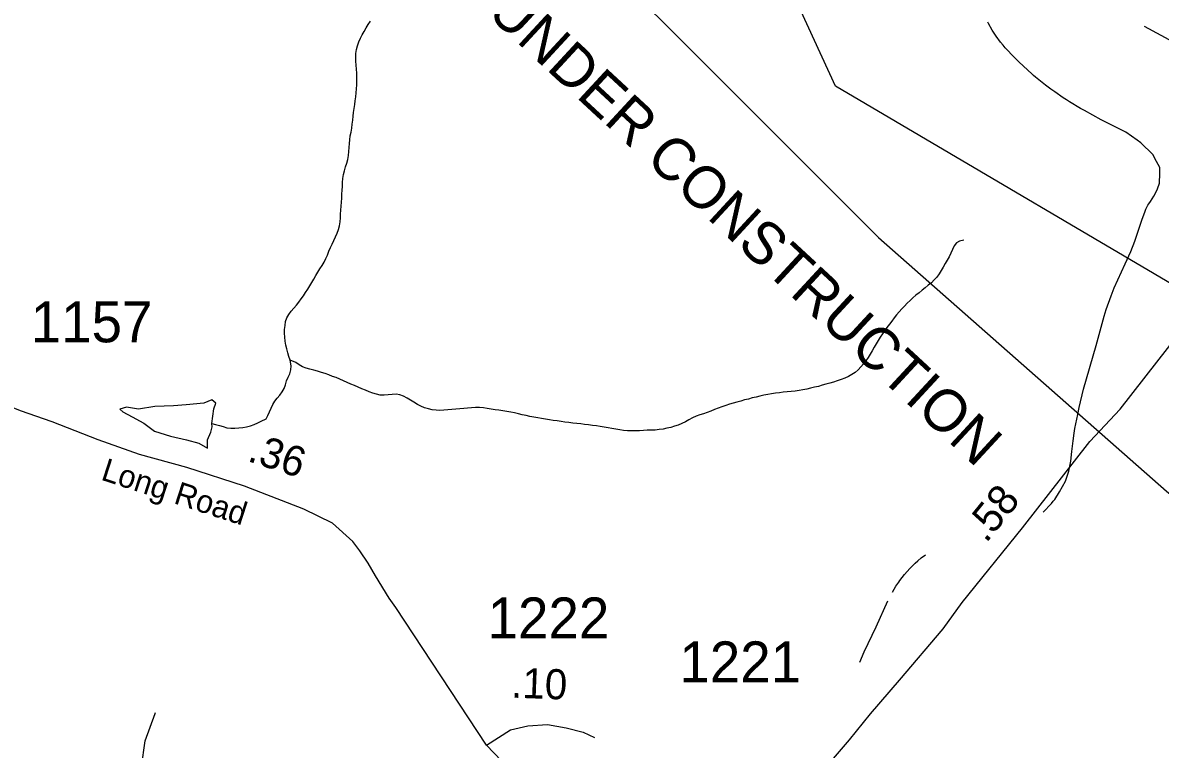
# Model space of a CAD drawing. Extents: x 1950930 to 2061844, y 904556 to 1017002.
# Drawn here: x 1991711 to 1996439, y 955325 to 958343 of the extents above; entities that cross this region are included whole.
import ezdxf

# ---------------------------------------------------------------- set-up
doc = ezdxf.new("R2010")
doc.units = 0
for name, color, linetype in [('Exist Hydrographic Creek Single Shore', 7, 'Continuous'), ('Exist Hydrographic Misc Water Feature', 7, 'Continuous'), ('Exist Road Primary Interstate Shield CELL', 7, 'Continuous'), ('Exist Road Primary NC Attributed', 7, 'Continuous'), ('Exist Road Primary NC Service Mileage Hundredths English Label', 7, 'Continuous'), ('Exist Road Primary US Structure Standard Bridge CELL', 7, 'Continuous'), ('Exist Road Secondary Structure Standard Bridge Number Label', 7, 'Continuous'), ('Exist Road Secondary Type 51 Attributed', 7, 'Continuous'), ('Exist Road Secondary Type 51 Label', 7, 'Continuous'), ('Exist Road Secondary Type 51 Number Label', 7, 'Continuous'), ('Prop Road Primary NC Projected', 7, 'Continuous')]:
    doc.layers.add(name, color=color, linetype=linetype)

msp = doc.modelspace()

# ---------------------------------------------------------------- linework, layer by layer
at = {"layer": 'Exist Hydrographic Creek Single Shore'}
for points in [[(1992823.3, 956941), (1992817.9, 956956.6), (1992812.8, 956972.3), (1992808.9, 956988), (1992805.4, 957003.7), (1992802.6, 957020.2), (1992800.5, 957036.6), (1992799.7, 957053), (1992799.9, 957069.5), (1992801.5, 957085.9), (1992803.6, 957102.2), (1992808.5, 957117.7), (1992816.7, 957131.6), (1992827, 957144.4), (1992838, 957157.3), (1992849.1, 957169.4), (1992859, 957182.3), (1992868.6, 957196), (1992877.8, 957209), (1992887, 957222.8), (1992895.9, 957236.5), (1992904.7, 957250.3), (1992913.3, 957264.8), (1992921.7, 957278.7), (1992929.7, 957293.2), (1992938.1, 957307), (1992946.5, 957320.8), (1992955.3, 957335.4), (1992963.7, 957349.1), (1992971.1, 957363.8), (1992977.7, 957378.4), (1992984, 957393.9), (1992990.4, 957409.3), (1992997, 957424), (1993003.9, 957438.6), (1993010.7, 957454), (1993017.5, 957468.7), (1993024.2, 957484), (1993028.3, 957499.6), (1993030.2, 957515.9), (1993031.4, 957532.4), (1993032.6, 957548.7), (1993033.7, 957565.1), (1993034.7, 957581.5), (1993035.7, 957597.9), (1993036.9, 957614.2), (1993038, 957630.8), (1993038.8, 957647.1), (1993039.6, 957663.5), (1993040.6, 957679.9), (1993042.3, 957696.2), (1993044.3, 957712.6), (1993048.2, 957728.1), (1993052.9, 957744.4), (1993057.9, 957759.9), (1993062, 957775.4), (1993064.8, 957791.8), (1993066.5, 957808.1), (1993067.7, 957824.5), (1993068.7, 957840.9), (1993070.4, 957857.2), (1993072.8, 957873.6), (1993075.7, 957889.1), (1993078.8, 957905.5), (1993081, 957921.9), (1993082.9, 957938.2), (1993084.5, 957954.6), (1993086.4, 957971), (1993088.2, 957987.3), (1993090.9, 958003.7), (1993093.3, 958019.3), (1993095.2, 958035.6), (1993097, 958052), (1993098, 958068.4), (1993099.3, 958084.7), (1993100.1, 958101.1), (1993100.1, 958117.5), (1993099.3, 958134.1), (1993098, 958150.5), (1993096.4, 958166.9), (1993095.4, 958183.3), (1993095.2, 958199.8), (1993095.6, 958216.1), (1993098, 958232.5), (1993102.4, 958248), (1993107.9, 958263.4), (1993114.7, 958278.9), (1993121.8, 958293.6), (1993130, 958307.3), (1993138.9, 958321.9), (1993147.5, 958335.6), (1993156.1, 958349.5)], [(1992722.8, 956697.8), (1992730.6, 956712.3), (1992737.4, 956727), (1992744.1, 956741.6), (1992751.3, 956757), (1992759.3, 956770.9), (1992769.1, 956783.8), (1992779.8, 956796.7), (1992789.2, 956809.6), (1992797.4, 956824.3), (1992803, 956839.7), (1992807.3, 956856), (1992813.8, 956870.6), (1992820.8, 956885.3), (1992824.9, 956901.6), (1992827.2, 956917.9), (1992823.3, 956941)], [(1994307, 956650.2), (1994290.6, 956649.8), (1994274.2, 956648.5), (1994257.8, 956647.9), (1994241.4, 956647.4), (1994224.8, 956647.8), (1994208.6, 956649.8), (1994192.4, 956651.7), (1994176.2, 956654.6), (1994160.2, 956657.4), (1994144, 956661), (1994127.8, 956663.7), (1994111.8, 956666.6), (1994095.4, 956668.5), (1994079.2, 956670.5), (1994062.8, 956672.5), (1994046.4, 956674.5), (1994030.2, 956676.4), (1994013.8, 956678.5), (1993997.6, 956680.3), (1993981.4, 956682.4), (1993965, 956684.3), (1993948.8, 956687.2), (1993932.6, 956689.2), (1993916.4, 956691.1), (1993900.2, 956694), (1993883.8, 956696.7), (1993867.6, 956698.7), (1993851.6, 956701.5), (1993835.4, 956705.1), (1993819.4, 956707.9), (1993803.4, 956711.5), (1993787.4, 956715.1), (1993771.2, 956718.8), (1993755.2, 956722.4), (1993739.2, 956725.1), (1993722.8, 956727.9), (1993706.6, 956730.8), (1993690.4, 956733.5), (1993674.4, 956735.5), (1993658.3, 956738.4), (1993641.8, 956741.1), (1993625.9, 956743.9), (1993609.4, 956745), (1993593, 956744.5), (1993576.8, 956744.1), (1993560.2, 956742.8), (1993544, 956740.7), (1993527.6, 956739.4), (1993511.2, 956738.1), (1993494.8, 956736.7), (1993478.2, 956735.4), (1993461.8, 956733.3), (1993445.4, 956732.8), (1993429.2, 956733.2), (1993413, 956735.2), (1993397.2, 956738.8), (1993381.4, 956744), (1993366.1, 956751), (1993351.5, 956757.7), (1993336.9, 956766.4), (1993323, 956774.8), (1993308.6, 956784.1), (1993294.3, 956791.8), (1993279.1, 956797), (1993263.7, 956799.8), (1993246.9, 956799.3), (1993230.3, 956797.2), (1993213.5, 956796), (1993197.3, 956796.3), (1993181.7, 956799.9), (1993165.9, 956805.1), (1993150.5, 956810.3), (1993135.4, 956816.4), (1993120.2, 956822.4), (1993104.8, 956829.3), (1993089.6, 956836.3), (1993074.7, 956842.2), (1993059.3, 956848.3), (1993044.5, 956855.1), (1993029.6, 956862), (1993014.4, 956869), (1992999.2, 956874.2), (1992983.8, 956880.3), (1992968.2, 956885.5), (1992952.5, 956890.7), (1992936.9, 956895.2), (1992920.9, 956899.6), (1992905.1, 956904), (1992889.3, 956908.5), (1992873.9, 956913.7), (1992860, 956922.2), (1992846, 956931.5), (1992823.3, 956941)]]:
    msp.add_lwpolyline(points, dxfattribs=at)
at = {"layer": 'Exist Hydrographic Misc Water Feature'}
for p, q in [((1995724.6, 958340.5), (1995721.9, 958345.8)), ((1996206.6, 957933.2), (1996193.5, 957940.3)), ((1996357.6, 957844.4), (1996343.4, 957854.8)), ((1996425.6, 957648.7), (1996427.3, 957653.3)), ((1996375.6, 957560.7), (1996379.3, 957568.3))]:
    msp.add_line(p, q, dxfattribs=at)
for points in [[(1995757.6, 958286.9), (1995740.6, 958312.7), (1995724.6, 958340.5)], [(1995757.6, 958286.9), (1995740.6, 958312.7), (1995724.6, 958340.5)], [(1995786.1, 958249.4), (1995775.6, 958262.6), (1995757.6, 958286.9)], [(1995786.1, 958249.4), (1995775.6, 958262.6), (1995757.6, 958286.9)], [(1995803.9, 958228.7), (1995794.7, 958238.7), (1995786.1, 958249.4)], [(1995803.9, 958228.7), (1995794.7, 958238.7), (1995786.1, 958249.4)], [(1995912.6, 958124), (1995904.6, 958131), (1995852.7, 958179.1), (1995822.8, 958208.7), (1995803.9, 958228.7)], [(1995912.6, 958124), (1995904.6, 958131), (1995852.7, 958179.1), (1995822.8, 958208.7), (1995803.9, 958228.7)], [(1996000.2, 958055.9), (1995984.6, 958066.9), (1995962.6, 958083.7), (1995920.6, 958117.2), (1995912.6, 958124)], [(1996000.2, 958055.9), (1995984.6, 958066.9), (1995962.6, 958083.7), (1995920.6, 958117.2), (1995912.6, 958124)], [(1996049, 958022.4), (1996035.6, 958030.9), (1996000.2, 958055.9)], [(1996049, 958022.4), (1996035.6, 958030.9), (1996000.2, 958055.9)], [(1996107.6, 957987.5), (1996061.7, 958014.3), (1996049, 958022.4)], [(1996107.6, 957987.5), (1996061.7, 958014.3), (1996049, 958022.4)], [(1996193.5, 957940.3), (1996123.6, 957978.2), (1996107.6, 957987.5)], [(1996193.5, 957940.3), (1996123.6, 957978.2), (1996107.6, 957987.5)], [(1996343.4, 957854.8), (1996296.5, 957889.1), (1996206.6, 957933.2)], [(1996343.4, 957854.8), (1996296.5, 957889.1), (1996206.6, 957933.2)], [(1996423.8, 957767.1), (1996407.6, 957796.3), (1996357.6, 957844.4)], [(1996423.8, 957767.1), (1996407.6, 957796.3), (1996357.6, 957844.4)], [(1996436.9, 957716.4), (1996437.7, 957741.9), (1996423.8, 957767.1)], [(1996436.9, 957716.4), (1996437.7, 957741.9), (1996423.8, 957767.1)], [(1996427.3, 957653.3), (1996435.9, 957677.2), (1996436.9, 957716.4)], [(1996427.3, 957653.3), (1996435.9, 957677.2), (1996436.9, 957716.4)], [(1996405.5, 957612.3), (1996411.9, 957622.3), (1996425.6, 957648.7)], [(1996405.5, 957612.3), (1996411.9, 957622.3), (1996425.6, 957648.7)], [(1996379.3, 957568.3), (1996387.7, 957585.4), (1996392, 957591.5)], [(1996379.3, 957568.3), (1996387.7, 957585.4), (1996392, 957591.5)], [(1996392, 957591.5), (1996398.4, 957600.9), (1996405.5, 957612.3)], [(1996392, 957591.5), (1996398.4, 957600.9), (1996405.5, 957612.3)], [(1996293.2, 957342), (1996316.5, 957392.6), (1996333.6, 957435.9), (1996362.7, 957523.5), (1996375.6, 957560.7)], [(1995622.2, 957440.2), (1995605.2, 957436.5), (1995591.5, 957429.4), (1995582.9, 957416.4), (1995575.3, 957401.8), (1995568.3, 957386.3), (1995561.5, 957370.9), (1995553.5, 957356.3), (1995545.5, 957342.5), (1995536.9, 957327.9), (1995528.3, 957314.2), (1995519.7, 957300.3), (1995510.1, 957286.6), (1995499.4, 957274.6), (1995487.7, 957263.3), (1995474.6, 957252.9), (1995461.7, 957242.5), (1995449, 957233), (1995436.3, 957221.7), (1995423.7, 957211.3), (1995411.2, 957200.9), (1995398.9, 957189.7), (1995387, 957178.4), (1995375.6, 957166.3), (1995364.5, 957155.1), (1995353.6, 957142.1), (1995343.2, 957130.1), (1995332.9, 957117.2), (1995322.9, 957104.2), (1995313, 957090.4), (1995303.2, 957077.6), (1995293.7, 957064.7), (1995284.3, 957050.9), (1995275.1, 957037.1), (1995266.1, 957023.4), (1995257.9, 957009.5), (1995249.7, 956995), (1995241.9, 956980.4), (1995233.9, 956966.6), (1995224.8, 956952.9), (1995215.2, 956939.1), (1995205, 956926.2), (1995194.3, 956913.3), (1995182.8, 956902), (1995170.7, 956890.8), (1995157.2, 956882), (1995142.6, 956874.1), (1995127.4, 956867.1), (1995112.1, 956861.6), (1995096.5, 956856.2), (1995081.1, 956850.7), (1995065.3, 956846.2), (1995049.3, 956841.6), (1995033.7, 956837), (1995018, 956832.4), (1995001.8, 956828.7), (1994986, 956824.9), (1994969.8, 956821.1), (1994953.8, 956818.1), (1994937.8, 956816), (1994921.4, 956813.1), (1994905, 956811.8), (1994888.8, 956809.6), (1994872.4, 956808.3), (1994856.2, 956806.2), (1994839.6, 956804.1), (1994823.4, 956801.9), (1994807.4, 956799.1), (1994791.4, 956796.1), (1994775.2, 956792.3), (1994759.2, 956788.5), (1994743.4, 956784.8), (1994727.4, 956780.2), (1994711.6, 956776.4), (1994695.8, 956771.8), (1994679.8, 956767.2), (1994664.2, 956762.6), (1994648.4, 956758.1), (1994632.9, 956753.4), (1994617.5, 956748), (1994602.1, 956741.8), (1994586.7, 956736.3), (1994571.3, 956730.1), (1994555.8, 956724.6), (1994540.2, 956719.2), (1994524.8, 956713.9), (1994509.6, 956708.4), (1994494.9, 956701.4), (1994480.3, 956693.4), (1994466, 956685.5), (1994451, 956678.4), (1994435.6, 956672.1), (1994420.2, 956666.8), (1994404.4, 956662.1), (1994388.6, 956658.4), (1994372.4, 956654.6), (1994356.2, 956653.4), (1994339.8, 956651.2), (1994323.4, 956650.7), (1994307, 956650.2)], [(1996235.3, 957208.7), (1996247.6, 957242.3), (1996262.6, 957275.9), (1996293.2, 957342)], [(1996205.6, 957124.5), (1996214.4, 957152.4), (1996235.3, 957208.7)], [(1996095.7, 956716.1), (1996101.7, 956744.9), (1996120.5, 956820.4), (1996172.6, 957002.4), (1996205.6, 957124.5)], [(1992496.6, 956678.7), (1992506.1, 956739.2), (1992513.9, 956762.8), (1992497.9, 956777.1), (1992464, 956763), (1992390, 956756.4), (1992338.3, 956751.7), (1992260.2, 956748.4), (1992192.5, 956738.3), (1992142.3, 956745.9), (1992114.4, 956737.4), (1992126.7, 956727.4), (1992166.7, 956706), (1992214.9, 956680.3), (1992259.2, 956646.7), (1992325.4, 956625.6), (1992391.4, 956610.3), (1992443.5, 956596.9), (1992479.8, 956576.4), (1992479.6, 956610.9), (1992493.1, 956642.6), (1992498.9, 956664.7), (1992496.6, 956678.7)], [(1996080.9, 956637.8), (1996083.6, 956658), (1996095.7, 956716.1)], [(1992496.6, 956678.7), (1992512.6, 956674.3), (1992528.6, 956669.8), (1992544.4, 956665.4), (1992560.2, 956661), (1992576.2, 956658.9), (1992592.6, 956658.6), (1992608.8, 956659.9), (1992625.4, 956662.1), (1992641.6, 956665), (1992657.8, 956668.8), (1992673, 956674.2), (1992688.1, 956681.3), (1992702.9, 956688.3), (1992722.8, 956697.8)], [(1996071.9, 956562.6), (1996076.6, 956606.8), (1996080.9, 956637.8)], [(1996044.6, 956439.1), (1996059.6, 956480.7), (1996067.6, 956521.7), (1996071.9, 956562.6)], [(1995994.2, 956355.1), (1996000.6, 956363.1), (1996020.7, 956394.8), (1996033, 956416.9), (1996044.6, 956439.1)], [(1995952.8, 956310.5), (1995987.6, 956346.5), (1995994.2, 956355.1)], [(1995397.7, 956075.5), (1995420.7, 956098.8), (1995431.3, 956108.3)], [(1995431.3, 956108.3), (1995444.7, 956120.3), (1995463.5, 956132.5)], [(1995352, 956019.8), (1995356.7, 956026.4), (1995375.8, 956050.8), (1995397.7, 956075.5)], [(1995325.7, 955977.6), (1995339.7, 956002.3), (1995352, 956019.8)], [(1995190.6, 955686.7), (1995208.4, 955730.4), (1995257.7, 955833.8), (1995306.7, 955942)], [(1991010.6, 951952.4), (1990976.7, 952028.6), (1990968.7, 952327.5), (1991260.7, 952820.2), (1992128.7, 954712.4), (1992220.6, 955360.3), (1992261.3, 955474)], [(1992261.3, 955474), (1992262.6, 955477.6)]]:
    msp.add_lwpolyline(points, dxfattribs=at)
at = {"layer": 'Exist Road Primary NC Attributed'}
msp.add_lwpolyline([(1994675.4, 954742.1), (1994890.9, 955049.2), (1994989.1, 955157.2), (1995072.9, 955277.5), (1995147.3, 955365), (1995234.1, 955472.9), (1995355.4, 955612.3), (1995536.5, 955826), (1995615, 955935.1), (1995865.9, 956244.8), (1996145.7, 956603.2), (1996272.7, 956737.8), (1996576.7, 957128.3)], dxfattribs=at)
at = {"layer": 'Exist Road Secondary Structure Standard Bridge Number Label'}
msp.add_lwpolyline([(1996764.5, 957093.3), (1995089.3, 958079.2), (1994653.1, 959030.3)], dxfattribs=at)
at = {"layer": 'Exist Road Secondary Type 51 Attributed'}
for points in [[(1993638.4, 955342), (1993261.4, 955914.6), (1993234.3, 955952.8), (1993177.1, 956046.2), (1993146.3, 956098.7), (1993113, 956149.6), (1993083.5, 956188), (1992998.3, 956264.3), (1992880.1, 956323.2), (1992632.3, 956417.8), (1992393, 956496.3), (1992196.3, 956549.9), (1992024.3, 956610.6), (1991834.3, 956685.6), (1991702.1, 956731.4), (1991609.8, 956768.6)], [(1993638.4, 955342), (1993739.1, 955405.3), (1993811, 955422.6), (1993891.6, 955428.4), (1993969.2, 955414), (1994041.1, 955396.7), (1994087.2, 955373.7)], [(1994551.9, 954501.6), (1994518.7, 954528.4), (1994481.1, 954559.9), (1994441.2, 954597.6), (1994205.1, 954789.5), (1994055.5, 954939.2), (1993970.7, 955009.7), (1993828.3, 955143.5), (1993638.4, 955342)]]:
    msp.add_lwpolyline(points, dxfattribs=at)
at = {"layer": 'Exist Road Secondary Type 51 Number Label'}
msp.add_line((1997566.6, 957682.3), (1996373.3, 958327.8), dxfattribs=at)
at = {"layer": 'Prop Road Primary NC Projected'}
msp.add_lwpolyline([(1991892.5, 959975.9), (1992556, 959745.1), (1993118.4, 959398.7), (1993637.7, 959052.4), (1994358.8, 958359.8), (1995267.4, 957450.8), (1996464.5, 956397.4), (1997113.5, 955878), (1997935.6, 955358.5), (1998700, 955069.9), (1999377.8, 954896.8), (1999969.1, 954738.1), (2002273.7, 954377.2), (2004312.5, 954167.5), (2005551, 954186.6), (2006258.5, 953742.2)], dxfattribs=at)

# ---------------------------------------------------------------- texts
at = {"layer": 'Exist Road Primary Interstate Shield CELL'}
msp.add_text('PROPOSED/UNDER CONSTRUCTION', height=175, rotation=317.2188, dxfattribs=at).set_placement((1992613.9, 959326.1))
at = {"layer": 'Exist Road Primary NC Service Mileage Hundredths English Label'}
msp.add_text('.58', height=125, rotation=50.9616, dxfattribs=at).set_placement((1995714.9, 956178.5))
at = {"layer": 'Exist Road Primary US Structure Standard Bridge CELL'}
for s, rotation, p in [('.36', 341.8417, (1992640.8, 956523.6)), ('.10', 357.8802, (1993739.8, 955539.8))]:
    msp.add_text(s, height=125, rotation=rotation, dxfattribs=at).set_placement(p)
at = {"layer": 'Exist Road Secondary Type 51 Label'}
msp.add_text('Long Road', height=95, rotation=342.075, dxfattribs=at).set_placement((1992032.2, 956445.9))
at = {"layer": 'Exist Road Secondary Type 51 Number Label'}
for s, p in [('1157', (1991744.6, 957015.7)), ('1222', (1993643.5, 955785.8)), ('1221', (1994440.5, 955603.2))]:
    msp.add_text(s, height=170, dxfattribs=at).set_placement(p)

doc.saveas('drawing.dxf')
